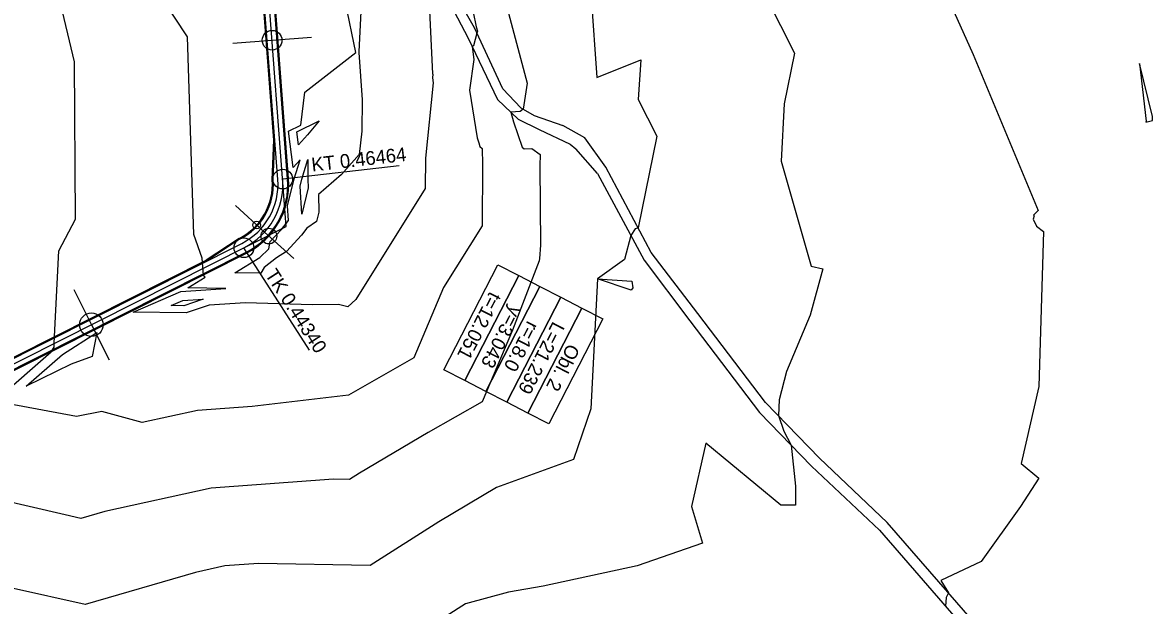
# Model space of a CAD drawing. Extents: x -549394 to -546608, y -1037055 to -1033629.
# Drawn here: x -547938.3 to -547651.3, y -1034859.6 to -1034711.6 of the extents above; entities that cross this region are included whole.
import ezdxf

# ---------------------------------------------------------------- set-up
doc = ezdxf.new("R2010")
doc.units = 0
for name, color, linetype in [('hlavni_vrst', 7, 'Continuous'), ('hrana_L', 7, 'Continuous'), ('norm_vrst', 7, 'Continuous'), ('POLYGONY_SITUACE_PO', 7, 'Continuous'), ('u_sirka_1_0m', 7, 'Continuous'), ('u_sirka_1_5m', 7, 'Continuous'), ('x_navrh_C121', 7, 'Continuous'), ('x_osa_C121', 7, 'Continuous'), ('x_popis_oblouky_C121', 7, 'Continuous'), ('x_popis_pricne_rezy_C121', 7, 'Continuous')]:
    doc.layers.add(name, color=color, linetype=linetype)

msp = doc.modelspace()

# ---------------------------------------------------------------- linework, layer by layer
at = {"layer": 'hlavni_vrst'}
for p, q in [((-547925.09, -1034721.59), (-547933.58, -1034685.98)), ((-547825.93, -1034698.92), (-547823.08, -1034712.7)), ((-547822.95, -1034714.28), (-547823.74, -1034717.53)), ((-547823.08, -1034712.7), (-547822.79, -1034713.78)), ((-547822.79, -1034713.78), (-547822.95, -1034714.28)), ((-547823.74, -1034717.53), (-547824.08, -1034717.68)), ((-547824.08, -1034717.68), (-547823.71, -1034721)), ((-547823.71, -1034721), (-547824.8, -1034728.76)), ((-547924.9, -1034761.54), (-547925.09, -1034721.59)), ((-547651.32, -1034735.47), (-547654.56, -1034721.99)), ((-547654.56, -1034721.99), (-547652.92, -1034736.68)), ((-547824.8, -1034728.76), (-547822.8, -1034740.91)), ((-547651.33, -1034736.48), (-547651.32, -1034735.47)), ((-547652.97, -1034736.94), (-547651.33, -1034736.48)), ((-547652.92, -1034736.68), (-547652.97, -1034736.94)), ((-547822.8, -1034740.91), (-547822.44, -1034742.18)), ((-547822.44, -1034742.18), (-547822.12, -1034743.12)), ((-547822.12, -1034743.12), (-547821.56, -1034743.61)), ((-547821.56, -1034743.61), (-547821.51, -1034747.7)), ((-547821.51, -1034747.7), (-547821.6, -1034763.26)), ((-547929.09, -1034769.59), (-547924.9, -1034761.54)), ((-547821.6, -1034763.26), (-547831.37, -1034778.88)), ((-547930.28, -1034793.03), (-547929.09, -1034769.59)), ((-547831.37, -1034778.88), (-547838.89, -1034796.79)), ((-547951.64, -1034813.16), (-547931.04, -1034795.2)), ((-547931.04, -1034795.2), (-547930.29, -1034794.03)), ((-547930.29, -1034794.03), (-547930.28, -1034793.03)), ((-547838.89, -1034796.79), (-547855.54, -1034806.2)), ((-547855.54, -1034806.2), (-547879.97, -1034809.11)), ((-547924.61, -1034811.63), (-547941.92, -1034808.45)), ((-547879.97, -1034809.11), (-547893.86, -1034810.13)), ((-547918.17, -1034810.42), (-547924.61, -1034811.63)), ((-547907.91, -1034813.21), (-547918.17, -1034810.42)), ((-547893.86, -1034810.13), (-547907.91, -1034813.21))]:
    msp.add_line(p, q, dxfattribs=at)
at = {"layer": 'hrana_L'}
for p, q in [((-547834.9, -1034696.97), (-547825.09, -1034715.55)), ((-547823.55, -1034712.99), (-547832.97, -1034696.15)), ((-547816.3, -1034728.43), (-547823.55, -1034712.99)), ((-547825.09, -1034715.55), (-547817.65, -1034731.14)), ((-547816.3, -1034728.43), (-547811.71, -1034733.28)), ((-547817.65, -1034731.14), (-547812.44, -1034736.16)), ((-547811.71, -1034733.28), (-547808.35, -1034735.19)), ((-547808.35, -1034735.19), (-547801.05, -1034737.8)), ((-547812.44, -1034736.16), (-547807.11, -1034738.8)), ((-547795.47, -1034740.88), (-547801.05, -1034737.8)), ((-547807.11, -1034738.8), (-547799.21, -1034742.53)), ((-547790.15, -1034748.33), (-547795.47, -1034740.88)), ((-547799.21, -1034742.53), (-547797.77, -1034743.66)), ((-547792.27, -1034749.93), (-547797.77, -1034743.66)), ((-547778.63, -1034770.04), (-547790.15, -1034748.33)), ((-547792.27, -1034749.93), (-547780.43, -1034771.99)), ((-547780.43, -1034771.99), (-547768.8, -1034787.38)), ((-547766.75, -1034785.52), (-547778.63, -1034770.04)), ((-547749.58, -1034808.07), (-547766.75, -1034785.52)), ((-547768.8, -1034787.38), (-547751.14, -1034810.64)), ((-547735.85, -1034822.27), (-547749.58, -1034808.07)), ((-547751.14, -1034810.64), (-547737.91, -1034824.28)), ((-547737.91, -1034824.28), (-547720.62, -1034840.52)), ((-547718.69, -1034838.54), (-547735.85, -1034822.27)), ((-547680.8, -1034881.96), (-547718.69, -1034838.54)), ((-547720.62, -1034840.52), (-547683.3, -1034883.53))]:
    msp.add_line(p, q, dxfattribs=at)
at = {"layer": 'norm_vrst'}
for p, q in [((-547896.4, -1034715.27), (-547904.3, -1034703.2)), ((-547853.65, -1034719.19), (-547856.25, -1034706.52)), ((-547852.23, -1034705.46), (-547852.92, -1034718.94)), ((-547793.92, -1034704.37), (-547792.45, -1034725.58)), ((-547749.38, -1034705.22), (-547742.26, -1034719.39)), ((-547834.94, -1034708.62), (-547834.18, -1034724.62)), ((-547815.21, -1034707.93), (-547810.13, -1034727.01)), ((-547701.78, -1034708.8), (-547696.84, -1034719.69)), ((-547894.84, -1034765.45), (-547896.4, -1034715.27)), ((-547866.63, -1034729.29), (-547853.65, -1034719.19)), ((-547852.92, -1034718.94), (-547852.89, -1034719.21)), ((-547852.89, -1034719.21), (-547852.08, -1034731.24)), ((-547792.45, -1034725.58), (-547781.26, -1034721.09)), ((-547781.26, -1034721.09), (-547781.91, -1034731.18)), ((-547742.26, -1034719.39), (-547744.87, -1034732.23)), ((-547696.84, -1034719.69), (-547680.3, -1034759.35)), ((-547834.07, -1034724.69), (-547834.2, -1034725.62)), ((-547834.2, -1034725.62), (-547833.98, -1034726.93)), ((-547834.18, -1034724.62), (-547834.07, -1034724.69)), ((-547867.66, -1034737.67), (-547866.63, -1034729.29)), ((-547833.98, -1034726.93), (-547836, -1034746.08)), ((-547810.13, -1034727.01), (-547811.18, -1034733.58)), ((-547810.13, -1034727.01), (-547810.13, -1034727.01)), ((-547810.13, -1034727.01), (-547810.13, -1034727.01)), ((-547810.13, -1034727.01), (-547810.13, -1034727.01)), ((-547810.13, -1034727.01), (-547810.13, -1034727.01)), ((-547852.08, -1034731.24), (-547852.13, -1034739.18)), ((-547781.91, -1034731.18), (-547777.22, -1034740.51)), ((-547744.87, -1034732.23), (-547745.63, -1034746.85)), ((-547811.94, -1034734.19), (-547814.27, -1034734.4)), ((-547814.27, -1034734.4), (-547813.59, -1034736.85)), ((-547811.18, -1034733.58), (-547811.94, -1034734.19)), ((-547870.8, -1034739.17), (-547867.66, -1034737.67)), ((-547868.65, -1034739.34), (-547862.94, -1034736.6)), ((-547862.94, -1034736.6), (-547865.91, -1034740.13)), ((-547813.59, -1034736.85), (-547811.37, -1034743.27)), ((-547869.57, -1034748.4), (-547870.8, -1034739.17)), ((-547868.2, -1034742.69), (-547868.65, -1034739.34)), ((-547865.91, -1034740.13), (-547868.2, -1034742.69)), ((-547852.13, -1034739.18), (-547852.8, -1034745.12)), ((-547777.22, -1034740.51), (-547781.95, -1034763.78)), ((-547811.37, -1034743.27), (-547810.88, -1034743.7)), ((-547810.88, -1034743.7), (-547808.95, -1034743.64)), ((-547808.95, -1034743.64), (-547806.87, -1034745.11)), ((-547867.82, -1034746.44), (-547869.57, -1034748.4)), ((-547869.31, -1034751.27), (-547867.82, -1034746.44)), ((-547867.4, -1034751.41), (-547865.85, -1034746.4)), ((-547865.85, -1034746.4), (-547865.84, -1034751.37)), ((-547852.8, -1034745.12), (-547857.31, -1034750.17)), ((-547836, -1034746.08), (-547836.05, -1034753.79)), ((-547806.87, -1034745.11), (-547806.89, -1034747.97)), ((-547745.63, -1034746.85), (-547737.97, -1034773.44)), ((-547806.89, -1034747.97), (-547806.79, -1034768.14)), ((-547871.01, -1034758.14), (-547869.31, -1034751.27)), ((-547867.84, -1034753.19), (-547867.4, -1034751.41)), ((-547865.84, -1034751.37), (-547865.78, -1034753.61)), ((-547857.31, -1034750.17), (-547863.18, -1034755.25)), ((-547867.38, -1034760.26), (-547867.84, -1034753.19)), ((-547865.78, -1034753.61), (-547867.38, -1034760.26)), ((-547863.18, -1034755.25), (-547863.05, -1034759.74)), ((-547836.05, -1034753.79), (-547853.64, -1034781.94)), ((-547870.76, -1034761.88), (-547871.01, -1034758.14)), ((-547863.05, -1034759.74), (-547863.63, -1034762.16)), ((-547681.39, -1034760.72), (-547681.63, -1034761.55)), ((-547680.3, -1034759.35), (-547681.49, -1034760.5)), ((-547681.49, -1034760.5), (-547681.39, -1034760.72)), ((-547872.52, -1034764.2), (-547870.76, -1034761.88)), ((-547866.1, -1034763.84), (-547867.47, -1034765.63)), ((-547863.63, -1034762.16), (-547866.1, -1034763.84)), ((-547782.72, -1034764.01), (-547783.81, -1034765.69)), ((-547781.95, -1034763.78), (-547782.72, -1034764.01)), ((-547681.63, -1034761.55), (-547680.73, -1034763.36)), ((-547680.73, -1034763.36), (-547678.99, -1034764.7)), ((-547892.68, -1034771.41), (-547894.84, -1034765.45)), ((-547875.38, -1034767.23), (-547872.52, -1034764.2)), ((-547867.47, -1034765.63), (-547871.28, -1034769.73)), ((-547783.81, -1034765.69), (-547785.4, -1034771.76)), ((-547678.99, -1034764.7), (-547680.13, -1034804.07)), ((-547878.03, -1034771.25), (-547875.72, -1034769.06)), ((-547875.72, -1034769.06), (-547875.38, -1034767.23)), ((-547871.28, -1034769.73), (-547873.77, -1034771.38)), ((-547806.79, -1034768.14), (-547806.98, -1034771.55)), ((-547892.39, -1034775.78), (-547892.68, -1034771.41)), ((-547884.43, -1034775.15), (-547878.03, -1034771.25)), ((-547873.77, -1034771.38), (-547876.97, -1034773.79)), ((-547807.11, -1034772.14), (-547813.87, -1034789.74)), ((-547806.98, -1034771.55), (-547807.11, -1034772.14)), ((-547785.4, -1034771.76), (-547792.3, -1034776.68)), ((-547877.8, -1034775.24), (-547884.43, -1034775.15)), ((-547876.97, -1034773.79), (-547877.8, -1034775.24)), ((-547735.03, -1034774.12), (-547738.25, -1034785.92)), ((-547737.97, -1034773.44), (-547735.03, -1034774.12)), ((-547896.37, -1034779), (-547891.93, -1034776.3)), ((-547891.93, -1034776.3), (-547892.39, -1034775.78)), ((-547792.3, -1034776.68), (-547793.96, -1034809.67)), ((-547783.75, -1034779.6), (-547792.3, -1034776.68)), ((-547792.3, -1034776.68), (-547792.3, -1034776.68)), ((-547792.3, -1034776.68), (-547783.56, -1034777.29)), ((-547792.3, -1034776.68), (-547792.3, -1034776.68)), ((-547783.56, -1034777.29), (-547783.3, -1034778.97)), ((-547910.22, -1034785.17), (-547898.09, -1034779.92)), ((-547898.09, -1034779.92), (-547886.67, -1034779.14)), ((-547886.67, -1034779.14), (-547896.37, -1034779)), ((-547783.3, -1034778.97), (-547783.75, -1034779.6)), ((-547900.58, -1034783.49), (-547897.64, -1034782.22)), ((-547897.31, -1034783.52), (-547900.58, -1034783.49)), ((-547897.64, -1034782.22), (-547892.41, -1034781.86)), ((-547892.41, -1034781.86), (-547897.31, -1034783.52)), ((-547890.93, -1034783.34), (-547896.73, -1034785.31)), ((-547881.68, -1034782.83), (-547890.93, -1034783.34)), ((-547864.71, -1034783.27), (-547881.68, -1034782.83)), ((-547858.09, -1034783.17), (-547864.71, -1034783.27)), ((-547855.65, -1034783.84), (-547858.09, -1034783.17)), ((-547853.64, -1034781.94), (-547855.65, -1034783.84)), ((-547896.73, -1034785.31), (-547910.22, -1034785.17)), ((-547738.25, -1034785.92), (-547744.27, -1034800.19)), ((-547813.87, -1034789.74), (-547821.53, -1034807.96)), ((-547928.21, -1034795.9), (-547919.44, -1034790.29)), ((-547919.44, -1034790.29), (-547920.65, -1034796.4)), ((-547937.43, -1034803.93), (-547928.21, -1034795.9)), ((-547925.94, -1034798.36), (-547937.43, -1034803.93)), ((-547920.65, -1034796.4), (-547925.94, -1034798.36)), ((-547744.27, -1034800.19), (-547746.12, -1034807.44)), ((-547680.13, -1034804.07), (-547684.62, -1034823.6)), ((-547821.53, -1034807.96), (-547835.25, -1034815.72)), ((-547793.96, -1034809.67), (-547798.33, -1034822.53)), ((-547746.12, -1034807.44), (-547746.33, -1034811.43)), ((-547746.33, -1034811.43), (-547744.9, -1034815.39)), ((-547835.25, -1034815.72), (-547852.72, -1034826.06)), ((-547744.9, -1034815.39), (-547743.12, -1034818.91)), ((-547764.76, -1034818.45), (-547768.41, -1034834.52)), ((-547745.71, -1034834.13), (-547764.76, -1034818.45)), ((-547743.12, -1034818.91), (-547741.96, -1034829.33)), ((-547798.33, -1034822.53), (-547817.93, -1034829.7)), ((-547684.62, -1034823.6), (-547680.16, -1034827.29)), ((-547852.72, -1034826.06), (-547855.25, -1034827.67)), ((-547680.16, -1034827.29), (-547684.84, -1034834.54)), ((-547927.5, -1034836.66), (-547956.72, -1034829.83)), ((-547890.4, -1034829.87), (-547917.38, -1034835.78)), ((-547859.37, -1034827.6), (-547890.4, -1034829.87)), ((-547855.25, -1034827.67), (-547859.37, -1034827.6)), ((-547817.93, -1034829.7), (-547832.61, -1034838.39)), ((-547741.96, -1034829.33), (-547741.98, -1034834.14)), ((-547917.38, -1034835.78), (-547923.51, -1034837.56)), ((-547768.41, -1034834.52), (-547765.64, -1034843.85)), ((-547741.98, -1034834.14), (-547745.71, -1034834.13)), ((-547684.84, -1034834.54), (-547694.81, -1034848.48)), ((-547923.51, -1034837.56), (-547927.5, -1034836.66)), ((-547832.61, -1034838.39), (-547850.01, -1034849.47)), ((-547765.64, -1034843.85), (-547782.17, -1034849.57)), ((-547886.94, -1034849.61), (-547894.37, -1034851.24)), ((-547878.4, -1034848.98), (-547886.94, -1034849.61)), ((-547850.01, -1034849.47), (-547878.4, -1034848.98)), ((-547782.17, -1034849.57), (-547806.07, -1034854.69)), ((-547694.81, -1034848.48), (-547705.1, -1034853.29)), ((-547894.37, -1034851.24), (-547922.42, -1034859.39)), ((-547922.42, -1034859.39), (-547940.64, -1034855.29)), ((-547806.07, -1034854.69), (-547814.85, -1034856.23)), ((-547705.1, -1034853.29), (-547703.09, -1034856.42)), ((-547814.85, -1034856.23), (-547825.82, -1034859.2)), ((-547703.68, -1034857.63), (-547703.85, -1034859.84)), ((-547703.09, -1034856.42), (-547703.68, -1034857.63)), ((-547825.82, -1034859.2), (-547844.76, -1034871.27))]:
    msp.add_line(p, q, dxfattribs=at)
at = {"layer": 'POLYGONY_SITUACE_PO'}
for centre in [(-547872.23, -1034751.37), (-547882.08, -1034768.81)]:
    msp.add_circle(centre, 2.5, dxfattribs=at)
at = {"layer": 'u_sirka_1_0m'}
msp.add_circle((-547874.92, -1034716.1), 2.5, dxfattribs=at)
at = {"layer": 'u_sirka_1_5m'}
for centre, radius in [((-547878.84, -1034763.03), 1), ((-547875.74, -1034765.84), 2), ((-547920.83, -1034788.34), 3)]:
    msp.add_circle(centre, radius, dxfattribs=at)
at = {"layer": 'x_navrh_C121'}
for p, q in [((-547873.48, -1034751.46), (-547882.65, -1034631.03)), ((-547870.99, -1034751.27), (-547880.16, -1034630.84)), ((-547874.91, -1034751.55), (-547874.49, -1034741.49)), ((-547874.66, -1034751.55), (-547874.24, -1034741.49)), ((-547883.3, -1034766.42), (-547891.7, -1034771.97)), ((-547883.17, -1034766.64), (-547891.57, -1034772.19)), ((-548006.97, -1034830.35), (-547882.64, -1034767.69)), ((-548005.85, -1034832.58), (-547881.52, -1034769.92))]:
    msp.add_line(p, q, dxfattribs=at)
for points in [[(-547870.74, -1034751.25), (-547879.6, -1034634.9)], [(-547874.49, -1034741.49), (-547881.52, -1034649.21)], [(-548007.09, -1034830.13), (-547891.7, -1034771.97)], [(-547996.8, -1034828.3), (-547881.4, -1034770.15)]]:
    msp.add_lwpolyline(points, dxfattribs=at)
for radius, start, end in [(15.32, 296.6931, 4.4089), (15.57, 296.7478, 4.3542), (16.75, 296.7478, 4.3542), (19.25, 296.7478, 4.3542), (19.5, 296.7478, 4.3542)]:
    msp.add_arc((-547890.18, -1034752.73), radius, start, end, dxfattribs=at)
at = {"layer": 'x_osa_C121'}
for points in [[(-547871.32, -1034763.38), (-547881.69, -1034627.22), (-547879.74, -1034623.88)], [(-548015.16, -1034835.88), (-547871.32, -1034763.38)]]:
    msp.add_lwpolyline(points, dxfattribs=at)
msp.add_arc((-547890.18, -1034752.73), 18, 296.7478, 4.3542, dxfattribs=at)
at = {"layer": 'x_popis_oblouky_C121'}
for points in [[(-547842.64, -1034748), (-547872.23, -1034751.37)], [(-547865.4, -1034794.77), (-547882.08, -1034768.81)]]:
    msp.add_lwpolyline(points, dxfattribs=at)
for points in [[(-547812.25, -1034775.88), (-547825.98, -1034802.55), (-547831.32, -1034799.8), (-547817.59, -1034773.13)], [(-547806.92, -1034778.62), (-547820.65, -1034805.3), (-547825.98, -1034802.55), (-547812.25, -1034775.88)], [(-547801.58, -1034781.37), (-547815.31, -1034808.04), (-547820.65, -1034805.3), (-547806.92, -1034778.62)], [(-547796.25, -1034784.12), (-547809.98, -1034810.79), (-547815.31, -1034808.04), (-547801.58, -1034781.37)], [(-547790.91, -1034786.86), (-547804.65, -1034813.54), (-547809.98, -1034810.79), (-547796.25, -1034784.12)]]:
    msp.add_lwpolyline(points, close=True, dxfattribs=at)
at = {"layer": 'x_popis_pricne_rezy_C121'}
for points in [[(-547884.89, -1034716.86), (-547874.92, -1034716.1), (-547864.95, -1034715.34)], [(-547884.26, -1034758.11), (-547876.85, -1034764.83), (-547869.45, -1034771.55)], [(-547925.33, -1034779.41), (-547920.83, -1034788.34), (-547916.33, -1034797.27)]]:
    msp.add_lwpolyline(points, dxfattribs=at)

# ---------------------------------------------------------------- texts
at = {"layer": 'x_popis_oblouky_C121'}
for s, rotation, p in [('KT 0.46464', 6.4933, (-547864.74, -1034749.47)), ('TK 0.44340', 302.7198, (-547876.84, -1034775.59)), ('t=12.051', 242.7801, (-547819.62, -1034779.72)), ('y=3.043', 242.7801, (-547814.29, -1034783.25)), ('r=18.0', 242.7801, (-547810.05, -1034787.14)), ('L=21.239', 242.7801, (-547803.58, -1034787.32)), ('Obl. 2', 242.7801, (-547799.72, -1034792.92))]:
    msp.add_text(s, height=3.5, rotation=rotation, dxfattribs=at).set_placement(p)

doc.saveas('drawing.dxf')
